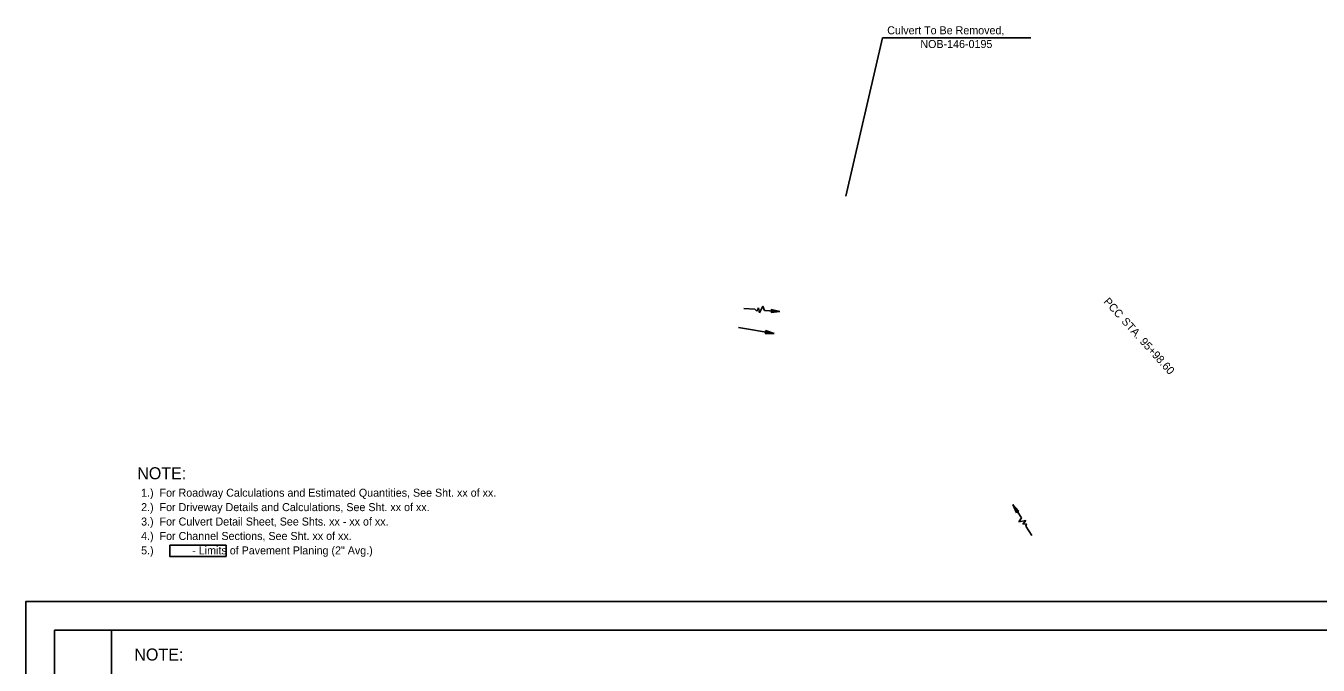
# Model space of a CAD drawing. Extents: x -231329 to 85860, y -286269 to 20577.
# Drawn here: x -9.9 to 442.2, y 411.1 to 634.6 of the extents above; entities that cross this region are included whole.
import ezdxf

# ---------------------------------------------------------------- set-up
doc = ezdxf.new("R2010")
doc.units = 0
for name, color, linetype in [('GE_P_Alignment', 7, 'Continuous'), ('GE_P_Alignment_100_Bearings', 7, 'Continuous'), ('GE_P_Alignment_100_Distances', 7, 'Continuous'), ('RW_X_CL', 7, 'Continuous'), ('RW_X_CL_100_Curve_Data', 7, 'Continuous'), ('RW_X_CL_100_Distances', 7, 'Continuous'), ('XS_P_Pavt_Surface', 7, 'Continuous')]:
    doc.layers.add(name, color=color, linetype=linetype)

msp = doc.modelspace()

# ---------------------------------------------------------------- linework, layer by layer
at = {"layer": 'GE_P_Alignment'}
for points in [[(0.06, 423.38), (20.06, 423.38), (20.06, 3.38), (0.06, 3.38)], [(20.06, 423.38), (660.06, 423.38), (660.06, 3.38), (20.06, 3.38)]]:
    msp.add_lwpolyline(points, close=True, dxfattribs=at)
at = {"layer": 'GE_P_Alignment_100_Distances'}
msp.add_lwpolyline([(40.39, 453.05), (60.13, 453.05), (60.13, 449.1), (40.39, 449.1)], close=True, dxfattribs=at)
at = {"layer": 'RW_X_CL'}
for q in [(276.94, 575.04), (341.66, 630.33)]:
    msp.add_line((289.72, 630.33), q, dxfattribs=at)
at = {"layer": 'RW_X_CL_100_Curve_Data'}
for p, q in [((245.14, 535.53), (241.22, 535.78)), ((245.73, 534.86), (245.14, 535.53)), ((246.33, 535.98), (245.73, 534.86)), ((246.75, 534.27), (246.33, 535.98)), ((247.84, 536.63), (246.75, 534.27)), ((248.44, 535.02), (247.84, 536.63)), ((253.89, 534.67), (248.44, 535.02)), ((253.89, 534.67), (250.78, 534.34)), ((250.78, 534.34), (250.78, 534.34)), ((250.85, 535.37), (250.85, 535.37)), ((250.85, 535.37), (253.89, 534.67)), ((251.82, 527.04), (239.34, 529.09)), ((251.82, 527.04), (248.68, 527.03)), ((248.68, 527.03), (248.69, 527.03)), ((248.86, 528.05), (248.86, 528.05)), ((248.86, 528.05), (251.82, 527.04)), ((335.38, 467.22), (338.34, 462.63)), ((336.63, 464.36), (335.38, 467.22)), ((335.38, 467.22), (337.5, 464.91)), ((336.63, 464.36), (336.63, 464.36)), ((338.34, 462.63), (337.41, 461.19)), ((337.41, 461.19), (339.95, 461.72)), ((337.5, 464.91), (337.5, 464.92)), ((339.95, 461.72), (338.83, 460.36)), ((338.83, 460.36), (340.09, 460.55)), ((340.09, 460.55), (339.91, 459.68)), ((339.91, 459.68), (342.04, 456.39))]:
    msp.add_line(p, q, dxfattribs=at)
for centre, start, end in [((250.03, 534.91), 322.727, 29.4078), ((248, 527.67), 316.8773, 23.5581), ((337.48, 463.98), 89.3185, 155.9992)]:
    msp.add_arc(centre, 0.938, start, end, dxfattribs=at)
at = {"layer": 'RW_X_CL_100_Distances'}
msp.add_lwpolyline([(-9.94, -6.62), (670.06, -6.62), (670.06, 433.38), (-9.94, 433.38)], close=True, dxfattribs=at)

# ---------------------------------------------------------------- texts
at = {"layer": 'GE_P_Alignment_100_Bearings'}
for s, p in [('Culvert To Be Removed,', (291.4, 631.62)), ('NOB-146-0195', (303, 626.82))]:
    msp.add_text(s, height=2.8, dxfattribs=at).set_placement(p)
at = {"layer": 'RW_X_CL'}
for s, height, p in [('NOTE:', 4.2, (29.03, 476.09)), ('1.)  For Roadway Calculations and Estimated Quantities, See Sht. xx of xx.', 2.8, (30.39, 469.99)), ('2.)  For Driveway Details and Calculations, See Sht. xx of xx.', 2.8, (30.39, 464.95)), ('3.)  For Culvert Detail Sheet, See Shts. xx - xx of xx.', 2.8, (30.39, 459.91)), ('4.)  For Channel Sections, See Sht. xx of xx.', 2.8, (30.39, 454.87)), ('5.)             - Limits of Pavement Planing (2" Avg.) ', 2.8, (30.39, 449.83)), ('NOTE:', 4.2, (28.01, 412.73))]:
    msp.add_text(s, height=height, dxfattribs=at).set_placement(p)
at = {"layer": 'XS_P_Pavt_Surface'}
for s, p in [('PCC', (366.9, 538.01)), (' STA. ', (372.45, 531.89)), ('95+98.60', (379.56, 524.05))]:
    msp.add_text(s, height=2.8, rotation=312.2154, dxfattribs=at).set_placement(p)

doc.saveas('drawing.dxf')
